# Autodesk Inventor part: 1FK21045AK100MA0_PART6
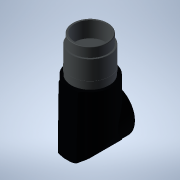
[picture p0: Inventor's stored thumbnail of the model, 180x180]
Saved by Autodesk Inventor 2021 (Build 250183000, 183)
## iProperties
Created: 2025-04
Part Number: 1FK21045AK100MA0_PART6
Material: Generic
Catalog Web Link: www.3dfindit.com
Description: -Servo synchronous motor
Document SubType Name: Modeling
Designer: psAdmin
Mass: 11.0817 g
Surface Area: 35.706 cm^2
Volume: 11.0817 cm^3
Density: 1 g/cm^3
Appearance: PSOLRGB-176-176-176
Category: PARTsolutions
Title: 1FK21045AK100MA0_PART6
Author: Cadenas PARTsolutions
Comments: Servo synchronous motor
Sending System: PARTsolutions
Preprocessor: ST-DEVELOPER v19.3
PSOL_IDENT_0: {$CADENAS_DATA/23d-libs/siemens_ag/_cat_/e0/5f/1fk21045ak100ma0.prj},213 {VTYP=3D},{NB=1FK21045AK100
PSOL_IDENT_1: MA0_PART6},{LINA=1FK21045AK100MA0_PART6},{NN=1FK21045AK100MA0_PART6},{NOPRJ=TRUE},{DATE=19.08.2025 1
PSOL_IDENT_2: 4:01:03},{GEOMDATE=30.07.2025 02:01:57},{VERSION=},{LINEID=10},{WBVAR=},{WBNUMERIC=}  {NB=1FK21045AK
PSOL_IDENT_3: 100MA0_PART6},{LINA=1FK21045AK100MA0_PART6},{KT=DUMMY},{PREVIEW=../../../_pool_/0f/2c/p_d211_xx_0043
PSOL_IDENT_4: 8j.png},{DESCSHORT=SIMOTICS S-1FK2 HD, SINAMICS S210 3AC 400V-480V, 1.7 Nm, 6000 rpm},{DESCLONG=SIMO
PSOL_IDENT_5: TICS S-1FK2 HD servo motor M0=2.4 Nm; PN = 1.07 kW at nN=6000 rpm (380-480 V); PN = 0.75 kW at nN=30
PSOL_IDENT_6: 00 rpm (200-240 V); with holding brake; degree of protection IP64; cylindrical shaft D19x40mm; absol
PSOL_IDENT_7: ute encoder 22-bit + 12-bit multiturn (encoder AM22DQC); with OCC interface; plug size M17, rotatabl
PSOL_IDENT_8: e; SIMOTICS S-1FK2 servomotorfor a wide range of uses in industrial environments. SIMOTICS S‑1FK2 se
PSOL_IDENT_9: rvomotors are compact synchronous motors with a high dynamic performance that set themselves apart a
PSOL_IDENT_10: s a result of their high power density, degree of protection and overload capability. The motors are
PSOL_IDENT_11: available in two variants: as High Dynamic variant (highest dynamic performance as a result of the
PSOL_IDENT_12: low intrinsic moment of inertia for applications demanding a high dynamic performance with low moved
PSOL_IDENT_13: masses) - and as Compact variant (precise and stable closed-loop control for medium up to large mov
PSOL_IDENT_14: ed masses as a result of a medium intrinsic moment of inertia). SIMOTICSS‑1FK2 servomotors fully exp
PSOL_IDENT_15: loit their strengths in a system with the SINAMICSS210 frequency converter and simple connection usi
PSOL_IDENT_16: ng the one cable connection (OCC). Advantages include the short control and positioning times, fast
PSOL_IDENT_17: and precise correction of disturbing quantities as well as stable control with a high dynamic perfor
PSOL_IDENT_18: mance. The servo motors can be configured to address a wide range of requirements. For example with
PSOL_IDENT_19: and without holding brake, IP64 or IP65 degree of protection, singleturn or multiturn absolute encod
PSOL_IDENT_20: ers - to name just a few. Further, the servomotors are available in different shaft heights extendin
PSOL_IDENT_21: g from 20 to 100. A shaft sealing ring is available to achieve an IP65 degree of protection and for
PSOL_IDENT_22: subsequent mounting at the motor or as spare part. SIMOTICS - the optimum motor for each and every m
PSOL_IDENT_23: otion control application.},{INTNO=804766807114},{SUPPLIERALTNO=1FK2104-5AK10-0MA0},{MANUID=1FK21045
PSOL_IDENT_24: AK100MA0},{MANUNAME=Siemens},{MANUTYPEDESC=Synchronous motor 1FK2-HD 2,39 Nm},{AAU732=SIMOTICS},{AAO
PSOL_IDENT_25: 057=S-1FK2},{AAU734=SIMOTICS S-1FK2 HD servo motor M0=2.4 Nm; PN = 1.07 kW at nN=6000 rpm (380-480 V
PSOL_IDENT_26: ); PN = 0.75 kW at nN=3000 rpm (200-240 V); with holding brake; degree of protection IP64; cylindric
PSOL_IDENT_27: al shaft D19x40mm; absolute encoder 22-bit + 12-bit multiturn (encoder AM22DQC); with OCC interface;
PSOL_IDENT_28: plug size M17, rotatable;},{AAW338=Synchronous motor 1FK2-HD 2,39 Nm},{AAO742=SIMOTICS},{AAO663=404
PSOL_IDENT_29: 2948691236},{NOCUPEROU=1},{PRICEQUANTITY=1},{QUANTITYMIN=1},{QUANTITYINT=1},{CTN=85015100},{COO=DE},
PSOL_IDENT_30: {AAO676=1FK2104-5AK10-0MA0},{AAO677=Siemens AG},{ORDERUNIT=C62},{CONTENTUNIT=C62}
NB: 1FK21045AK100MA0_PART6
NT: Servo synchronous motor
NBSYN: $MANUID._PART6
LINA: 1FK21045AK100MA0_PART6
CATALOG: SIEMENS
PREVIEW: ../../../_pool_/0f/2c/p_d211_xx_00438j.png
DESCSHORT: SIMOTICS S-1FK2 HD, SINAMICS S210 3AC 400V-480V, 1.7 Nm, 6000 rpm
DESCLONG: SIMOTICS S-1FK2 HD servo motor M0=2.4 Nm; PN = 1.07 kW at nN=6000 rpm (380-480 V); PN = 0.75 kW at nN=3000 rpm (200-240 V); with holding brake; degree of protec
INTNO: 804766807114
SUPPLIERALTNO: 1FK2104-5AK10-0MA0
MANUID: 1FK21045AK100MA0
MANUNAME: Siemens
MANUTYPEDESC: Synchronous motor 1FK2-HD 2,39 Nm
AAU732: SIMOTICS
AAO057: S-1FK2
AAU734: SIMOTICS S-1FK2 HD servo motor M0=2.4 Nm; PN = 1.07 kW at nN=6000 rpm (380-480 V); PN = 0.75 kW at nN=3000 rpm (200-240 V); with holding brake; degree of protec
AAW338: Synchronous motor 1FK2-HD 2,39 Nm
AAO742: SIMOTICS
AAO663: 4042948691236.0
NOCUPEROU: 1
PRICEQUANTITY: 1
QUANTITYMIN: 1
QUANTITYINT: 1
CTN: 85015100
COO: DE
ARTICLENO: 1FK21045AK100MA0_PART6
BOMINFO: 1FK21045AK100MA0_PART6
CREATOR: CADENAS GmbH
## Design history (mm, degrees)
feature "2025_04_17_15_45_15_0086"
body "Solid1"
